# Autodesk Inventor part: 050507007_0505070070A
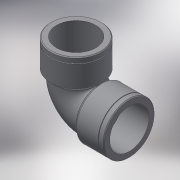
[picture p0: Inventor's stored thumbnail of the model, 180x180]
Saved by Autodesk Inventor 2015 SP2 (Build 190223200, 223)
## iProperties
Created: 2017-05
Part Number: 050507007_0505070070A
Material: Generic
Description: PLASSON THREADED ELBOW 3/4"-3/4"
Document SubType Name: Modeling
Designer: KIM
Density: 1 g/cm^3
Appearance: Default
Author: KIM
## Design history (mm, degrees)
derived "050507.ipt"
feature "Solid1::050507.ipt"
tag "TaggingFeature1"
body "Solid1"
other parameters: "d0" = 35, "d2" = 0.5, "d3" = 0.5, "d4" = 31.3521, "d5" = 24.117, "d6" = 18, "d7" = 135 deg, "d8" = 20.7, "d9" = 3.45, "d19" = 0.48234, "d27" = 18, "d30" = 21.7053, "d31" = 26.5287, "d33" = 90 deg, "d35" = 90 deg, "d36" = 90 deg, "d37" = 1.20585, "Rp_" = 24.117, "A_" = 35, "l_2" = 18
